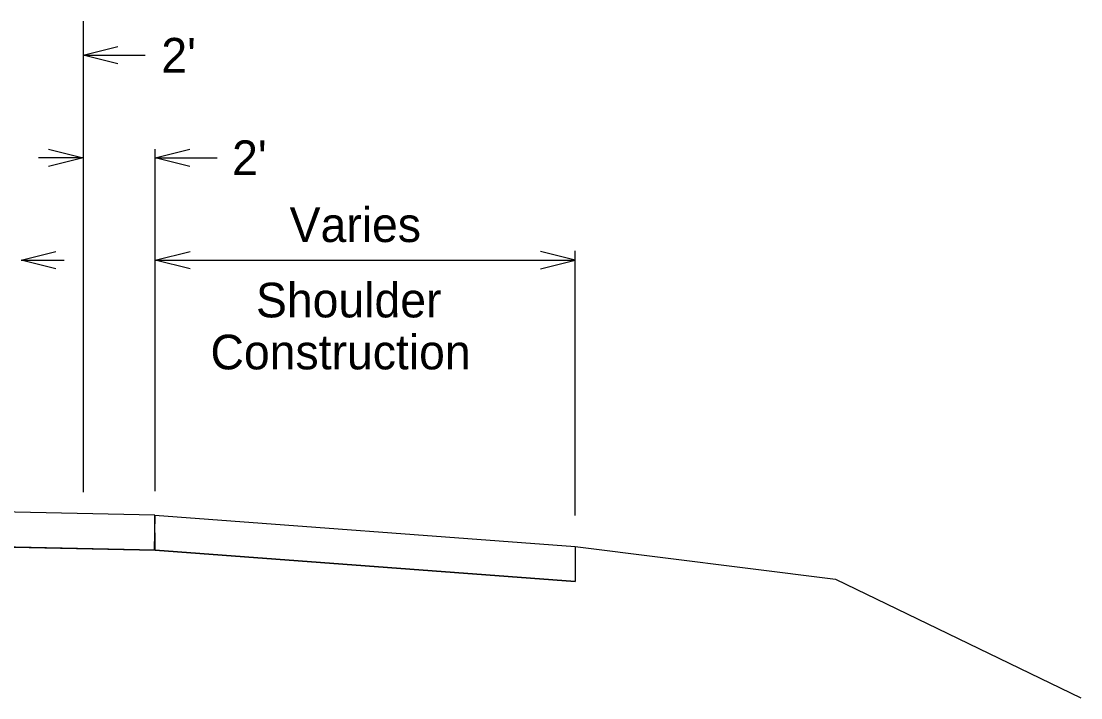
# Model space of a CAD drawing. Extents: x 10133 to 81668, y 4856 to 11018.
# Drawn here: x 13814 to 14315, y 5351 to 5671 of the extents above; entities that cross this region are included whole.
import ezdxf

# ---------------------------------------------------------------- set-up
doc = ezdxf.new("R2010")
doc.units = 0
for name, color, linetype in [('dsnXsPCCPavementBottom', 7, 'Continuous'), ('dsnXsShldrEarthFill', 7, 'Continuous'), ('dsnXsShldrGranular', 7, 'Continuous'), ('dsnXsShldrGranularBottom', 7, 'Continuous'), ('dsnXsShldrSpecialBackBottom', 7, 'Continuous')]:
    doc.layers.add(name, color=color, linetype=linetype)

msp = doc.modelspace()

# ---------------------------------------------------------------- linework, layer by layer
at = {"layer": 'dsnXsPCCPavementBottom'}
for p, q in [((13843.09, 5670.7), (13843.09, 5448.01)), ((13843.09, 5654.58), (13872.34, 5654.58)), ((13877.13, 5448.35), (13877.13, 5610.22)), ((13843.09, 5606.12), (13821.95, 5606.12)), ((13877.13, 5606.12), (13906.38, 5606.12)), ((13813.8, 5557.66), (13834.03, 5557.66)), ((13877.2, 5557.66), (14075.8, 5557.66)), ((14075.8, 5436.87), (14075.8, 5562.16))]:
    msp.add_line(p, q, dxfattribs=at)
for points in [[(13859.48, 5650.48), (13843.09, 5654.58), (13859.48, 5658.67)], [(13826.7, 5610.22), (13843.09, 5606.12), (13826.7, 5602.02)], [(13893.52, 5602.02), (13877.13, 5606.12), (13893.52, 5610.22)], [(13830.19, 5553.57), (13813.8, 5557.66), (13830.19, 5561.76)], [(13893.6, 5553.57), (13877.2, 5557.66), (13893.6, 5561.76)], [(14059.41, 5553.57), (14075.8, 5557.66), (14059.41, 5561.76)]]:
    msp.add_lwpolyline(points, dxfattribs=at)
at = {"layer": 'dsnXsShldrGranular'}
msp.add_line((13678.11, 5424.75), (13877.13, 5420.52), dxfattribs=at)
msp.add_lwpolyline([(13877.13, 5420.52), (13876.89, 5437.08), (13678.46, 5441.3)], dxfattribs=at)
msp.add_lwpolyline([(13876.89, 5437.08), (14075.8, 5422.28), (14075.8, 5405.68), (13877.13, 5420.46)], close=True, dxfattribs=at)
at = {"layer": 'dsnXsShldrGranularBottom'}
for p, q in [((13876.89, 5437.08), (13876.72, 5420.52)), ((14075.8, 5422.28), (14198.91, 5406.81)), ((14198.91, 5406.81), (14314.9, 5350.69))]:
    msp.add_line(p, q, dxfattribs=at)
at = {"layer": 'dsnXsShldrSpecialBackBottom'}
for p, q in [((13876.89, 5437.08), (14075.8, 5422.28)), ((13877.13, 5420.46), (14075.8, 5405.68)), ((14075.8, 5422.28), (14075.8, 5405.68))]:
    msp.add_line(p, q, dxfattribs=at)
for points in [[(13876.89, 5437.08), (13678.46, 5441.3), (13480.02, 5437.08), (13382.38, 5429.81)], [(13877.13, 5420.52), (13678.81, 5424.75), (13480.02, 5420.48), (13382.38, 5413.21)]]:
    msp.add_lwpolyline(points, dxfattribs=at)

# ---------------------------------------------------------------- texts
at = {"layer": 'dsnXsShldrEarthFill'}
for s, height, p in [("2'", 16.391, (13880.04, 5646.38)), ("2'", 16.391, (13913.51, 5597.92)), ('Varies', 16.391, (13940.71, 5566.25)), ('Shoulder ', 16.391, (13924.8, 5530.61)), ('Construction', 16.3906, (13903.28, 5506.03))]:
    msp.add_text(s, height=height, dxfattribs=at).set_placement(p)

doc.saveas('drawing.dxf')
